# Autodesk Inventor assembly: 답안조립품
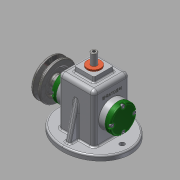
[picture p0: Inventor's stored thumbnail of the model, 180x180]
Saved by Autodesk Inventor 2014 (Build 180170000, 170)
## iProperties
Created: 2017-07
Part Number: 답안조립품
Document SubType Name: Assembly
Designer: 702-10
Author: 702-10
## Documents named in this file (16)
- C:\Users\702-10\Desktop\470708V1009\답안조립품.iam
- C:\Users\702-10\Desktop\470708V1009\본체.ipt
- C:\Users\702-10\Desktop\470708V1009\뒤커버.ipt
- C:\Users\702-10\Desktop\470708V1009\앞커버.ipt
- C:\Users\702-10\Desktop\470708V1009\부시.ipt
- C:\Users\702-10\Desktop\470708V1009\베어링 12 x 32 x 10.ipt
- C:\Users\702-10\Desktop\470708V1009\오일실 12 25 7.ipt
- C:\Users\702-10\Desktop\470708V1009\키 4 x 4 x 10.ipt
- C:\Users\702-10\Desktop\470708V1009\편심축.ipt
- C:\Users\702-10\Desktop\470708V1009\링크.ipt
- C:\Users\702-10\Desktop\470708V1009\슬라이드.ipt
- C:\Users\702-10\Desktop\470708V1009\핀 5 x 18.ipt
- C:\Users\702-10\Desktop\470708V1009\고정핀 1.2 x  8.ipt
- C:\Users\702-10\Desktop\470708V1009\V벨트풀리.ipt
- C:\Users\702-10\Desktop\470708V1009\멈춤나사 M3x8.ipt
- C:\Users\702-10\Desktop\470708V1009\볼트 M4 x 12.ipt
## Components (3 placed, 3 different names)
1. 핀 5 x 18:1
2. 고정핀 1.2 x  8:1
3. V벨트풀리:1 — 각도:2
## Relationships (1: Angle 1)
- 각도:2 [Angle]: V벨트풀리:1
